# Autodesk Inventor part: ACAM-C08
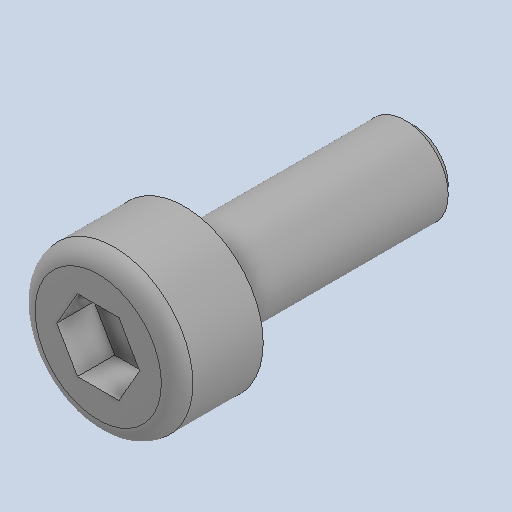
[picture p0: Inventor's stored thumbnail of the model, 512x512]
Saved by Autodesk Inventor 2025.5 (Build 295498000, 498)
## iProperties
Created: 2020-02
Part Number: ACAM-C08
Material: Genérico
Description: Tornillo Allen M3×8
Document SubType Name: Modeling
Designer: Luis MuÃ±oz
Authority: Unknown
Density: 1 g/cm^3
Appearance: Valor por defecto
Project: TESIS 2 - Plataforma mecatrÃ³nica preventiva desacoplada
Sending System: FreeCAD
Preprocessor: Open CASCADE STEP processor 7.3
Material_BOM: Por especificar
Proceso_BOM: Comercial
Title: Tornillo de cabeza cilÃ­ndrica con hexÃ¡gono interior M3 Ã— 8 mm
Author: Author
Revision Number: 00
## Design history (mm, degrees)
feature "Base1"
node "Sólido1"
